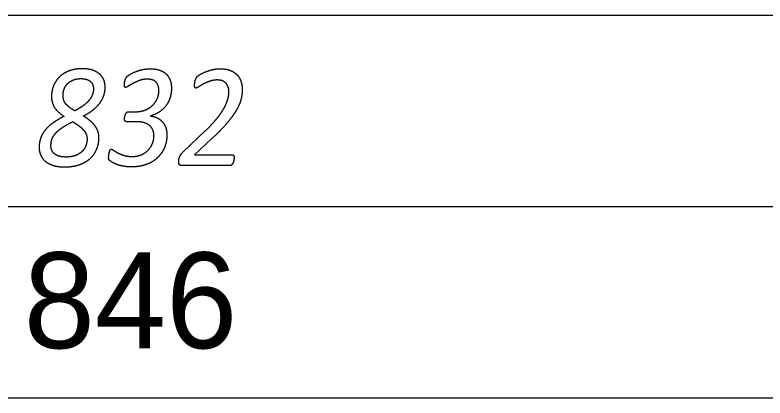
# Model space of a CAD drawing. Extents: x -14196 to 143, y -6096 to 28.
# Drawn here: x 91.113 to 92.093, y -5.829 to -5.329 of the extents above; entities that cross this region are included whole.
import ezdxf

# ---------------------------------------------------------------- set-up
doc = ezdxf.new("R2010")
doc.units = 0
doc.layers.add('RS_Raster1', color=7, linetype='Continuous')
doc.layers.add('SH_Text', color=7, linetype='Continuous')

msp = doc.modelspace()

# ---------------------------------------------------------------- linework, layer by layer
at = {"layer": 'RS_Raster1'}
for p, q in [((81.09453, -5.32886), (94.54453, -5.32886)), ((81.09453, -5.57886), (94.54453, -5.57886)), ((81.09453, -5.82886), (94.54453, -5.82886))]:
    msp.add_line(p, q, dxfattribs=at)
at = {"layer": 'SH_Text'}
for p, q in [((91.21568, -5.42499), (91.21568, -5.42499)), ((91.26127, -5.45511), (91.27122, -5.45511)), ((91.2901, -5.46057), (91.2901, -5.46077)), ((91.27131, -5.46814), (91.25908, -5.46814)), ((91.33222, -5.50804), (91.36169, -5.48)), ((91.20726, -5.49071), (91.20726, -5.49071)), ((91.22281, -5.48936), (91.22281, -5.48936)), ((91.31157, -5.48566), (91.31157, -5.48566)), ((91.39935, -5.51517), (91.39935, -5.51517)), ((91.39431, -5.5253), (91.33099, -5.5253))]:
    msp.add_line(p, q, dxfattribs=at)
msp.add_lwpolyline([(91.36983, -5.49068), (91.34766, -5.51122), (91.39661, -5.51122)], dxfattribs=at)
for points in [[(91.17793, -5.40459), (91.17346, -5.40719), (91.17024, -5.41065)], [(91.18809, -5.4005), (91.18239, -5.40199), (91.17793, -5.40459)], [(91.20096, -5.39901), (91.1938, -5.39901), (91.18809, -5.4005)], [(91.21566, -5.40132), (91.20991, -5.39901), (91.20096, -5.39901)], [(91.22484, -5.40714), (91.22142, -5.40363), (91.21566, -5.40132)], [(91.25931, -5.40934), (91.26028, -5.40829), (91.26311, -5.40652)], [(91.26311, -5.40652), (91.26594, -5.40475), (91.27001, -5.40308)], [(91.27001, -5.40308), (91.27408, -5.4014), (91.27916, -5.40021)], [(91.27916, -5.40021), (91.28425, -5.39901), (91.28964, -5.39901)], [(91.28964, -5.39901), (91.29663, -5.39901), (91.30189, -5.40079)], [(91.30189, -5.40079), (91.30716, -5.40258), (91.31061, -5.4059)], [(91.31061, -5.4059), (91.31406, -5.40922), (91.31578, -5.41399)], [(91.35117, -5.40922), (91.35214, -5.40816), (91.35502, -5.40643)], [(91.35502, -5.40643), (91.35789, -5.40469), (91.36196, -5.40306)], [(91.36196, -5.40306), (91.36603, -5.40142), (91.37099, -5.40021)], [(91.37099, -5.40021), (91.37594, -5.39901), (91.38125, -5.39901)], [(91.38125, -5.39901), (91.38975, -5.39901), (91.39533, -5.40161)], [(91.39533, -5.40161), (91.40091, -5.4042), (91.40414, -5.40815)], [(91.17024, -5.41065), (91.16701, -5.41412), (91.16493, -5.41811)], [(91.18142, -5.41889), (91.18425, -5.41586), (91.18867, -5.41389)], [(91.18867, -5.41389), (91.19309, -5.41192), (91.19927, -5.41192)], [(91.19927, -5.41192), (91.20388, -5.41192), (91.20703, -5.41303)], [(91.20703, -5.41303), (91.21018, -5.41413), (91.21209, -5.41601)], [(91.21209, -5.41601), (91.21399, -5.41788), (91.21484, -5.42023)], [(91.22958, -5.41484), (91.22825, -5.41065), (91.22484, -5.40714)], [(91.2309, -5.42297), (91.2309, -5.41903), (91.22958, -5.41484)], [(91.25613, -5.41812), (91.25631, -5.41667), (91.2567, -5.41503)], [(91.2567, -5.41503), (91.2571, -5.41339), (91.25776, -5.41185)], [(91.25776, -5.41185), (91.25842, -5.4103), (91.25931, -5.40934)], [(91.27593, -5.41431), (91.27133, -5.416), (91.26762, -5.41798)], [(91.28558, -5.41263), (91.28054, -5.41263), (91.27593, -5.41431)], [(91.2975, -5.41658), (91.29391, -5.41263), (91.28558, -5.41263)], [(91.31578, -5.41399), (91.3175, -5.41876), (91.3175, -5.42464)], [(91.34803, -5.41683), (91.34816, -5.41577), (91.34847, -5.41471)], [(91.34847, -5.41471), (91.34878, -5.41365), (91.34918, -5.41269)], [(91.34918, -5.41269), (91.34958, -5.41173), (91.35006, -5.41081)], [(91.35006, -5.41081), (91.35055, -5.4099), (91.35117, -5.40922)], [(91.36762, -5.41531), (91.36302, -5.41695), (91.3593, -5.41891)], [(91.37726, -5.41368), (91.37222, -5.41368), (91.36762, -5.41531)], [(91.38491, -5.41522), (91.38188, -5.41368), (91.37726, -5.41368)], [(91.38957, -5.41905), (91.38793, -5.41675), (91.38491, -5.41522)], [(91.40414, -5.40815), (91.40737, -5.41209), (91.40865, -5.41671)], [(91.16493, -5.41811), (91.16286, -5.42211), (91.16184, -5.42643)], [(91.17594, -5.43336), (91.17594, -5.42971), (91.17727, -5.42581)], [(91.17727, -5.42581), (91.17859, -5.42192), (91.18142, -5.41889)], [(91.21568, -5.42499), (91.21568, -5.42951), (91.214, -5.43351)], [(91.21484, -5.42023), (91.21568, -5.42259), (91.21568, -5.42499)], [(91.22882, -5.43481), (91.2309, -5.42932), (91.2309, -5.42297)], [(91.25596, -5.42034), (91.25596, -5.41957), (91.25613, -5.41812)], [(91.25639, -5.4226), (91.25596, -5.42178), (91.25596, -5.42034)], [(91.25762, -5.42342), (91.25683, -5.42342), (91.25639, -5.4226)], [(91.26129, -5.42169), (91.25868, -5.42342), (91.25762, -5.42342)], [(91.26762, -5.41798), (91.2639, -5.41995), (91.26129, -5.42169)], [(91.30109, -5.4274), (91.30109, -5.42054), (91.2975, -5.41658)], [(91.3175, -5.42464), (91.3175, -5.43138), (91.31552, -5.43731)], [(91.34763, -5.42049), (91.34763, -5.41972), (91.34776, -5.4188)], [(91.34816, -5.42328), (91.34763, -5.42232), (91.34763, -5.42049)], [(91.34776, -5.4188), (91.3479, -5.41789), (91.34803, -5.41683)], [(91.34957, -5.42425), (91.34869, -5.42425), (91.34816, -5.42328)], [(91.35306, -5.42256), (91.35054, -5.42425), (91.34957, -5.42425)], [(91.3593, -5.41891), (91.35559, -5.42088), (91.35306, -5.42256)], [(91.39189, -5.42399), (91.39122, -5.42135), (91.38957, -5.41905)], [(91.39255, -5.42892), (91.39255, -5.42662), (91.39189, -5.42399)], [(91.40865, -5.41671), (91.40994, -5.42133), (91.40994, -5.42546)], [(91.40994, -5.42546), (91.40994, -5.42941), (91.40941, -5.43354)], [(91.16184, -5.42643), (91.16082, -5.43076), (91.16082, -5.43509)], [(91.16082, -5.43509), (91.16082, -5.44308), (91.16471, -5.44943)], [(91.17652, -5.43894), (91.17594, -5.43644), (91.17594, -5.43336)], [(91.214, -5.43351), (91.21231, -5.4375), (91.20917, -5.44111)], [(91.22306, -5.44496), (91.22674, -5.44029), (91.22882, -5.43481)], [(91.29888, -5.43812), (91.30109, -5.4331), (91.30109, -5.4274)], [(91.39069, -5.44027), (91.39184, -5.43681), (91.3922, -5.43397)], [(91.3922, -5.43397), (91.39255, -5.43114), (91.39255, -5.42892)], [(91.40941, -5.43354), (91.40887, -5.43768), (91.40733, -5.44225)], [(91.17868, -5.4438), (91.17709, -5.44144), (91.17652, -5.43894)], [(91.18324, -5.44856), (91.18027, -5.44616), (91.17868, -5.4438)], [(91.20917, -5.44111), (91.20603, -5.44472), (91.20147, -5.44784)], [(91.21412, -5.45352), (91.21939, -5.44962), (91.22306, -5.44496)], [(91.29271, -5.44695), (91.29666, -5.44314), (91.29888, -5.43812)], [(91.31552, -5.43731), (91.31353, -5.44323), (91.30986, -5.44786)], [(91.3875, -5.44792), (91.38954, -5.44374), (91.39069, -5.44027)], [(91.40733, -5.44225), (91.40578, -5.44682), (91.40299, -5.45191)], [(91.16471, -5.44943), (91.1686, -5.45578), (91.17727, -5.46117)], [(91.19106, -5.45395), (91.1862, -5.45097), (91.18324, -5.44856)], [(91.20147, -5.44784), (91.19691, -5.45097), (91.19106, -5.45395)], [(91.20238, -5.46079), (91.20885, -5.45742), (91.21412, -5.45352)], [(91.2596, -5.45559), (91.26031, -5.45511), (91.26127, -5.45511)], [(91.27122, -5.45511), (91.27778, -5.45511), (91.28327, -5.45294)], [(91.28327, -5.45294), (91.28877, -5.45077), (91.29271, -5.44695)], [(91.30986, -5.44786), (91.30619, -5.45248), (91.30115, -5.4558)], [(91.38204, -5.45706), (91.38546, -5.4521), (91.3875, -5.44792)], [(91.40299, -5.45191), (91.4002, -5.45701), (91.39573, -5.46293)], [(91.17727, -5.46117), (91.1694, -5.46502), (91.16329, -5.46935)], [(91.21175, -5.46733), (91.20786, -5.46406), (91.20238, -5.46079)], [(91.25617, -5.46469), (91.25617, -5.46402), (91.2563, -5.46297)], [(91.25692, -5.46733), (91.25617, -5.46651), (91.25617, -5.46469)], [(91.2563, -5.46297), (91.25643, -5.46192), (91.2567, -5.46091)], [(91.2567, -5.46091), (91.25696, -5.4599), (91.25736, -5.45885)], [(91.25736, -5.45885), (91.25776, -5.4578), (91.25833, -5.45693)], [(91.25833, -5.45693), (91.2589, -5.45607), (91.2596, -5.45559)], [(91.30115, -5.4558), (91.29611, -5.45913), (91.2901, -5.46057)], [(91.2901, -5.46077), (91.29593, -5.46144), (91.30004, -5.46379)], [(91.30004, -5.46379), (91.30415, -5.46615), (91.30671, -5.46956)], [(91.37362, -5.46773), (91.37863, -5.46201), (91.38204, -5.45706)], [(91.39573, -5.46293), (91.39126, -5.46884), (91.38493, -5.47572)], [(91.16329, -5.46935), (91.15719, -5.47368), (91.15303, -5.47864)], [(91.17477, -5.47599), (91.18026, -5.47224), (91.18868, -5.4682)], [(91.18868, -5.4682), (91.19372, -5.47127), (91.1973, -5.47402)], [(91.1973, -5.47402), (91.20089, -5.47676), (91.2031, -5.47945)], [(91.21807, -5.47411), (91.21564, -5.4706), (91.21175, -5.46733)], [(91.22166, -5.48138), (91.22051, -5.47763), (91.21807, -5.47411)], [(91.25908, -5.46814), (91.25767, -5.46814), (91.25692, -5.46733)], [(91.28204, -5.46959), (91.27758, -5.46814), (91.27131, -5.46814)], [(91.28927, -5.47348), (91.28649, -5.47103), (91.28204, -5.46959)], [(91.29333, -5.47931), (91.29205, -5.47594), (91.28927, -5.47348)], [(91.30671, -5.46956), (91.30927, -5.47297), (91.31042, -5.47715)], [(91.36169, -5.48), (91.36861, -5.47346), (91.37362, -5.46773)], [(91.15303, -5.47864), (91.14887, -5.48359), (91.14675, -5.48927)], [(91.1614, -5.49114), (91.16273, -5.48725), (91.166, -5.48349)], [(91.166, -5.48349), (91.16928, -5.47974), (91.17477, -5.47599)], [(91.2031, -5.47945), (91.20531, -5.48215), (91.20628, -5.48489)], [(91.20628, -5.48489), (91.20726, -5.48763), (91.20726, -5.49071)], [(91.22281, -5.48936), (91.22281, -5.48513), (91.22166, -5.48138)], [(91.29461, -5.48652), (91.29461, -5.48267), (91.29333, -5.47931)], [(91.31042, -5.47715), (91.31157, -5.48133), (91.31157, -5.48566)], [(91.38493, -5.47572), (91.3786, -5.4826), (91.36983, -5.49068)], [(91.14675, -5.48927), (91.14463, -5.49494), (91.14463, -5.50149)], [(91.16007, -5.49937), (91.16007, -5.49504), (91.1614, -5.49114)], [(91.20726, -5.49071), (91.20726, -5.49513), (91.20571, -5.49936)], [(91.22174, -5.49822), (91.22281, -5.49369), (91.22281, -5.48936)], [(91.29289, -5.496), (91.29461, -5.49124), (91.29461, -5.48652)], [(91.31157, -5.48566), (91.31157, -5.49037), (91.31046, -5.49527)], [(91.14463, -5.50149), (91.14463, -5.50688), (91.14662, -5.51159)], [(91.16104, -5.50499), (91.16007, -5.50225), (91.16007, -5.49937)], [(91.20571, -5.49936), (91.20416, -5.5036), (91.20084, -5.50691)], [(91.21842, -5.50697), (91.22068, -5.50274), (91.22174, -5.49822)], [(91.23784, -5.50468), (91.2384, -5.50406), (91.2391, -5.50406)], [(91.2391, -5.50406), (91.2399, -5.50406), (91.24198, -5.50555)], [(91.28764, -5.50466), (91.29117, -5.50077), (91.29289, -5.496)], [(91.31046, -5.49527), (91.30935, -5.50017), (91.30697, -5.50478)], [(91.14662, -5.51159), (91.1486, -5.51631), (91.15267, -5.51977)], [(91.16432, -5.5098), (91.16202, -5.50773), (91.16104, -5.50499)], [(91.17047, -5.51307), (91.16662, -5.51187), (91.16432, -5.5098)], [(91.18007, -5.51427), (91.17432, -5.51427), (91.17047, -5.51307)], [(91.19238, -5.51225), (91.18724, -5.51427), (91.18007, -5.51427)], [(91.20084, -5.50691), (91.19751, -5.51023), (91.19238, -5.51225)], [(91.21263, -5.51486), (91.21617, -5.51121), (91.21842, -5.50697)], [(91.23544, -5.51485), (91.23544, -5.51427), (91.23553, -5.51326)], [(91.23553, -5.51326), (91.23561, -5.51225), (91.23579, -5.51109)], [(91.23579, -5.51109), (91.23596, -5.50994), (91.23622, -5.50863)], [(91.23622, -5.50863), (91.23649, -5.50733), (91.23688, -5.50632)], [(91.23688, -5.50632), (91.23727, -5.50531), (91.23784, -5.50468)], [(91.24198, -5.50555), (91.24406, -5.50703), (91.24742, -5.50881)], [(91.24742, -5.50881), (91.25078, -5.51059), (91.25534, -5.51208)], [(91.25534, -5.51208), (91.25989, -5.51356), (91.26582, -5.51356)], [(91.26582, -5.51356), (91.27324, -5.51356), (91.27867, -5.51106)], [(91.27867, -5.51106), (91.2841, -5.50856), (91.28764, -5.50466)], [(91.30091, -5.51348), (91.29723, -5.51757), (91.29206, -5.5206)], [(91.30697, -5.50478), (91.30458, -5.5094), (91.30091, -5.51348)], [(91.3277, -5.51537), (91.32823, -5.51354), (91.32929, -5.51166)], [(91.32929, -5.51166), (91.33035, -5.50978), (91.33222, -5.50804)], [(91.39661, -5.51122), (91.39811, -5.51122), (91.39873, -5.51242)], [(91.39873, -5.51242), (91.39935, -5.51363), (91.39935, -5.51517)], [(91.15267, -5.51977), (91.15673, -5.52323), (91.16301, -5.52521)], [(91.19258, -5.52559), (91.19909, -5.52401), (91.20409, -5.52126)], [(91.20409, -5.52126), (91.20909, -5.51852), (91.21263, -5.51486)], [(91.236, -5.5176), (91.23544, -5.51639), (91.23544, -5.51485)], [(91.23786, -5.51967), (91.23656, -5.5188), (91.236, -5.5176)], [(91.24304, -5.52266), (91.24016, -5.52128), (91.23786, -5.51967)], [(91.24941, -5.52504), (91.24591, -5.52404), (91.24304, -5.52266)], [(91.29206, -5.5206), (91.28688, -5.52362), (91.28025, -5.5254)], [(91.3269, -5.52125), (91.3269, -5.52029), (91.32703, -5.51875)], [(91.32712, -5.52294), (91.3269, -5.52222), (91.3269, -5.52125)], [(91.32703, -5.51875), (91.32717, -5.5172), (91.3277, -5.51537)], [(91.32779, -5.52419), (91.32734, -5.52366), (91.32712, -5.52294)], [(91.39718, -5.52328), (91.39661, -5.52414), (91.3959, -5.52472)], [(91.39816, -5.52125), (91.39776, -5.52241), (91.39718, -5.52328)], [(91.39882, -5.51898), (91.39856, -5.52009), (91.39816, -5.52125)], [(91.39922, -5.51681), (91.39909, -5.51787), (91.39882, -5.51898)], [(91.39935, -5.51517), (91.39935, -5.51575), (91.39922, -5.51681)], [(91.16301, -5.52521), (91.16928, -5.52718), (91.17785, -5.52718)], [(91.17785, -5.52718), (91.18608, -5.52718), (91.19258, -5.52559)], [(91.25684, -5.52661), (91.25291, -5.52604), (91.24941, -5.52504)], [(91.26521, -5.52718), (91.26078, -5.52718), (91.25684, -5.52661)], [(91.28025, -5.5254), (91.27361, -5.52718), (91.26521, -5.52718)], [(91.32903, -5.52501), (91.32823, -5.52472), (91.32779, -5.52419)], [(91.33099, -5.5253), (91.32984, -5.5253), (91.32903, -5.52501)], [(91.3959, -5.52472), (91.39519, -5.5253), (91.39431, -5.5253)]]:
    msp.add_open_spline(points, degree=2, dxfattribs=at)

# ---------------------------------------------------------------- texts
msp.add_text('846', height=0.125, dxfattribs=at).set_placement((91.12453, -5.76386))

doc.saveas('drawing.dxf')
